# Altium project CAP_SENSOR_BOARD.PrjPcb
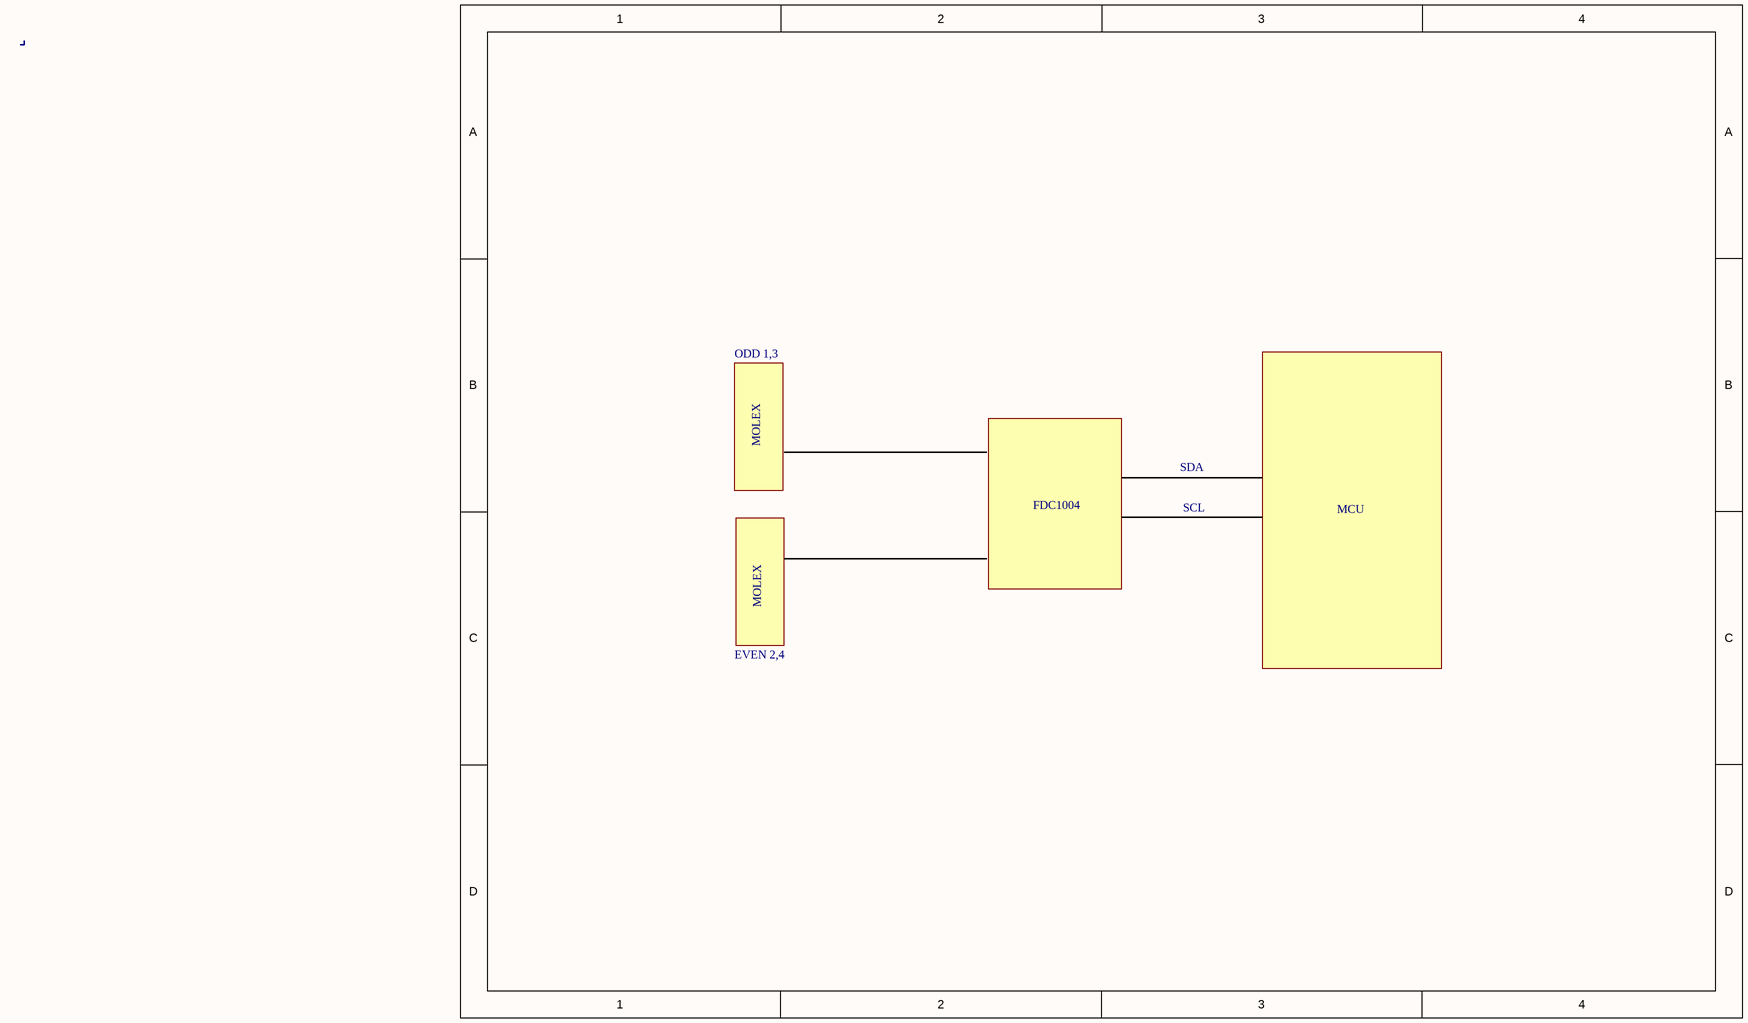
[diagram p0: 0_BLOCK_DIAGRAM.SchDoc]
5 sheets, 54 parts. Net scope: global (net labels, ports and power ports of the same name join across sheets).
Board file: CAP_SENSOR_BOARD.PcbDoc
Sheets:
  0_BLOCK_DIAGRAM.SchDoc
  1_POWER.SchDoc
  2_MCU.SchDoc
  3_PERIPHERAL.SchDoc
  5_UART.SchDoc

## Sheet 0_BLOCK_DIAGRAM.SchDoc
size A; SheetNumber: 1; SheetTotal: 5; ENG_APP_DATE: --/--/--; DSN_APP_DATE: --/--/--; CHK_APP_DATE: --/--/--

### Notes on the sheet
- ODD 1,3
- MOLEX
- SDA
- FDC1004
- SCL
- MCU
- EVEN 2,4

## Sheet 1_POWER.SchDoc: CAP SENSOR BOARD, PCBA
size A; DrawnBy: B. NGAI; Revision: X1; SheetNumber: 2; SheetTotal: 5; ENG_APP_DATE: --/--/--; DSN_APP_DATE: --/--/--; CHK_APP_DATE: --/--/--
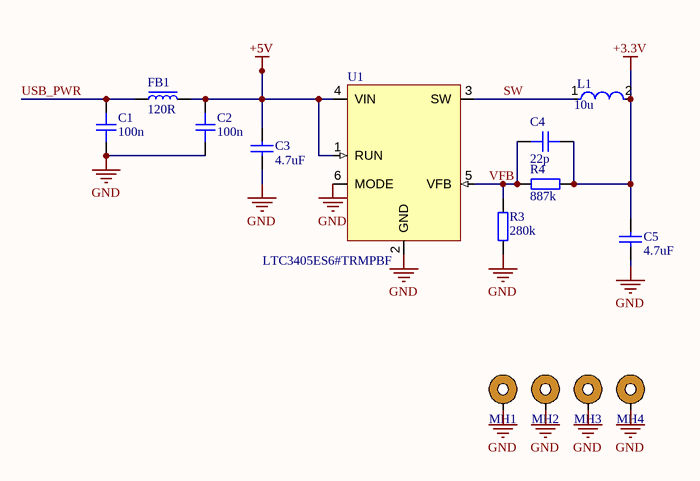
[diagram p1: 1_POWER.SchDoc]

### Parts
C1  100n  [CAP_0603]
C2  100n  [CAP_0603]
C3  4.7uF  [CAPC2013X140X50NL20T25]
C4  22p  [CAP_0603]
C5  4.7uF  [CAPC2013X140X50NL20T25]
FB1  120R  [FB_0603]
L1  10u  [FP-NRH2412-MFG]
MH1  M3-PTH  [MTG_M3_PTH_90317A112]  (value not drawn)  (no BOM)
MH2  M3-PTH  [MTG_M3_PTH_90317A112]  (value not drawn)  (no BOM)
MH3  M3-PTH  [MTG_M3_PTH_90317A112]  (value not drawn)  (no BOM)
MH4  M3-PTH  [MTG_M3_PTH_90317A112]  (value not drawn)  (no BOM)
R3  280k  [RES_0603]
R4  887k  [RES_0603]
U1  LTC3405ES6#TRMPBF  [SOT-23-6]

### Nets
+3.3V: C4.2 C5.2 L1.2 R4.2
+5V: C2.2 C3.2 FB1.2 U1.1(RUN) U1.4(VIN)
GND: C1.1 C2.1 C3.1 C5.1 MH1.1 MH2.1 MH3.1 MH4.1 R3.2 U1.2(GND) U1.6(MODE)
SW: L1.1 U1.3(SW)
USB_PWR: C1.2 FB1.1
VFB: C4.1 R3.1 R4.1 U1.5(VFB)

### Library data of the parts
C1 C2 C4 = CAP_0603: Capacitor SMD 0603
C3 C5 = CMP-2007-03298-1: Manufacturer: Kemet; Part Number: C0805C475K8RACTU
FB1 = FB_0603: Ferrite Bead SMD 0603
L1 = CMP-14484-000582-1: Shielded Wirewound Inductor 10uH 20% 0.51A 0.72Ω SMD; DC Resistance (DCR): 600mR; Current Rating: 450mA; Saturation Current: 810mA; Core Material: Ferrite; Test Frequency: 100kHz; Self Resonant Frequency: 29MHz
MH1-MH4 = MTG_M3_PTH_90317A112: Mounting Screw, M3 x 6mm, Internal Tooth Lock Washer, 90317A112; MFR 1: McMaster-Carr; Component: Mechanical; AJ PN: 30-1029
R3 R4 = RES_0603: Resistor SMD 0603
U1 = LTC3405ES6#TRMPBF: 1.5MHz, 300mA / Synchronous Step-Down / Regulator in ThinSOT; Manufacturer: Analog Devices

## Sheet 2_MCU.SchDoc: CAP SENSOR BOARD, PCBA
size A; DrawnBy: B. NGAI; Revision: X1; SheetNumber: 3; SheetTotal: 5; ENG_APP_DATE: --/--/--; DSN_APP_DATE: --/--/--; CHK_APP_DATE: --/--/--
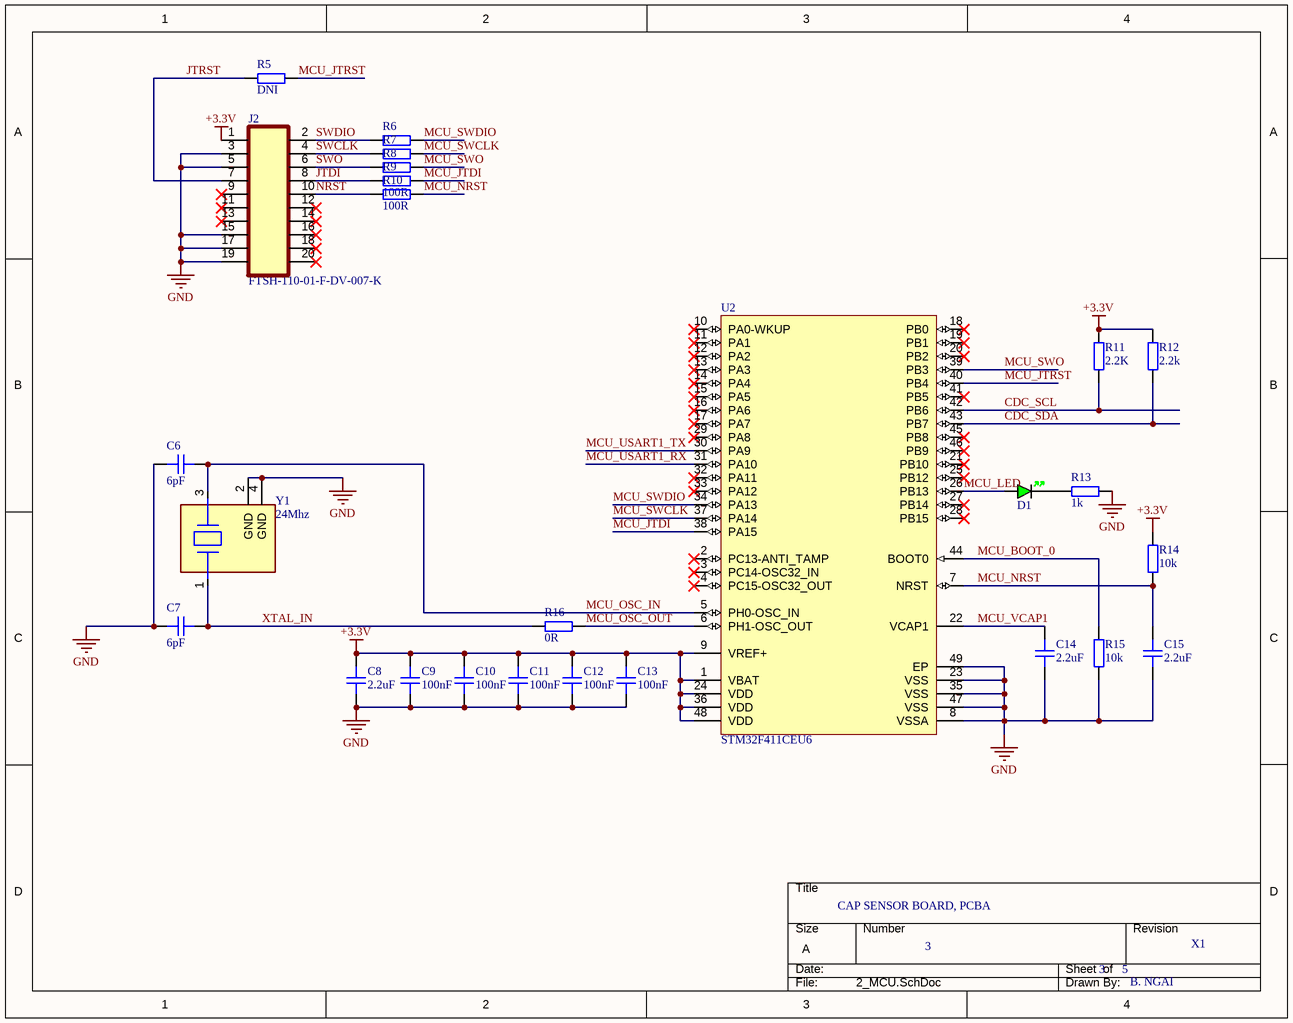
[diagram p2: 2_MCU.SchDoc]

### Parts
C6  6pF  [CAP_0402]
C7  6pF  [CAP_0402]
C8  2.2uF  [CAP_0603]
C9  100nF  [CAP_0402]
C10  100nF  [CAP_0402]
C11  100nF  [CAP_0402]
C12  100nF  [CAP_0402]
C13  100nF  [CAP_0402]
C14  2.2uF  [CAP_0603]
C15  2.2uF  [CAP_0402]
D1  GREEN  [LED_0402_GREEN]  (value not drawn)
J2  MFR 1 PN: FTSH-110-01-F-DV-007-K  [CN_20P_FTSH-110-01-F-DV-007-K]  (hidden comment: CN_20P_FTSH-110-01-F-DV-007-K)
R5  DNI  [RES_0603]
R6  100R  [RES_0402]  (value not drawn)
R7  100R  [RES_0402]  (value not drawn)
R8  100R  [RES_0402]  (value not drawn)
R9  100R  [RES_0402]
R10  100R  [RES_0402]
R11  2.2K  [RES_0402]
R12  2.2k  [RES_0402]
R13  1k  [RES_0603]
R14  10k  [RES_0402]
R15  10k  [RES_0402]
R16  0R  [RES_0402]
U2  STM32F411CEU6  [STM-UFQFPN48_L]
Y1  24Mhz  [FP-ECX-1637-MFG]

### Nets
+3.3V: C8.2 C9.2 C10.2 C11.2 C12.2 C13.2 J2.1 R11.2 R12.2 R14.2 U2.1(VBAT) U2.9(VREF+) U2.24(VDD) U2.36(VDD) U2.48(VDD)
GND: C6.2 C7.2 C8.1 C9.1 C10.1 C11.1 C12.1 C13.1 C14.1 C15.1 J2.3 J2.5 J2.15 J2.17 J2.19 R13.2 R15.1 U2.8(VSSA) U2.23(VSS) U2.35(VSS) U2.47(VSS) U2.49(EP) Y1.2(GND) Y1.4(GND)
CDC_SCL: R11.1 U2.42(PB6)
CDC_SDA: R12.1 U2.43(PB7)
JTDI: J2.8 R9.1
JTRST: J2.7 R5.1
MCU_BOOT_0: R15.2 U2.44(BOOT0)
MCU_JTDI: R9.2 U2.38(PA15)
MCU_JTRST: R5.2 U2.40(PB4)
MCU_LED: D1.A U2.26(PB13)
MCU_NRST: C15.2 R10.2 R14.1 U2.7(NRST)
MCU_OSC_IN: C6.1 U2.5(PH0-OSC_IN) Y1.3(Out/In)
MCU_OSC_OUT: R16.2 U2.6(PH1-OSC_OUT)
MCU_SWCLK: R7.2 U2.37(PA14)
MCU_SWDIO: R6.2 U2.34(PA13)
MCU_SWO: R8.2 U2.39(PB3)
MCU_USART1_RX: U2.31(PA10)
MCU_USART1_TX: U2.30(PA9)
MCU_VCAP1: C14.2 U2.22(VCAP1)
NRST: J2.10 R10.1
SWCLK: J2.4 R7.1
SWDIO: J2.2 R6.1
SWO: J2.6 R8.1
XTAL_IN: C7.1 R16.1 Y1.1(In/Out)
NetD1_K: D1.K R13.1

Not connected (* = marked no-connect by the designer): J2 9* 11* 12* 13* 14* 16* 18* 20*; U2 2(PC13-ANTI_TAMP)* 3(PC14-OSC32_IN)* 4(PC15-OSC32_OUT)* 10(PA0-WKUP)* 11(PA1)* 12(PA2)* 13(PA3)* 14(PA4)* 15(PA5)* 16(PA6)* 17(PA7)* 18(PB0)* 19(PB1)* 20(PB2)* 21(PB10)* 25(PB12)* 27(PB14)* 28(PB15)* 29(PA8)* 32(PA11)* 33(PA12)* 41(PB5)* 45(PB8)* 46(PB9)*

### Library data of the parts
C6 C7 C9-C13 C15 = CAP_0402: Capacitor SMD 0402
C8 C14 = CAP_0603: Capacitor SMD 0603
D1 = LED_0402_GREEN: LED 0402 GREEN SMD
J2 = CN_20P_FTSH-110-01-F-DV-007-K: Connector, Header, 20 Pos, 0.05" Pitch, Vertical, Keyed, SM; MFR 1: Samtec Inc.
R5 = RES_0603: DO NOT INSTALL
R6-R12 R14-R16 = RES_0402: Resistor SMD 0402
R13 = RES_0603: Resistor SMD 0603
U2 = CMP-0243-00165-1: ARM Cortex-M4 32-bit MCU+FPU, 512 KB Flash, 128 KB RAM, 36 I/Os, 48-Pin UFQFPN, -40 to 85 degC, Tray; Operating Frequency(F) (Processor speed) (MHz): 100; FLASH Size (Prog) (kB): 512; Internal RAM Size (kB): 128; I/Os (High Current): 36; Supply Voltage(Vcc) min (V): 1.7
Y1 = CMP-40224-000003-1: CRYSTAL 24.0000MHZ 8PF SMD; Manufacturer: ECS Inc.; Manufacturer Part Number: ECS-240-8-37CKM; Stability: 10ppm; Esr: 80Ω

## Sheet 3_PERIPHERAL.SchDoc: CAP SENSOR BOARD, PCBA
size A; DrawnBy: B. NGAI; Revision: X1; SheetNumber: 4; SheetTotal: 5; ENG_APP_DATE: --/--/--; DSN_APP_DATE: --/--/--; CHK_APP_DATE: --/--/--
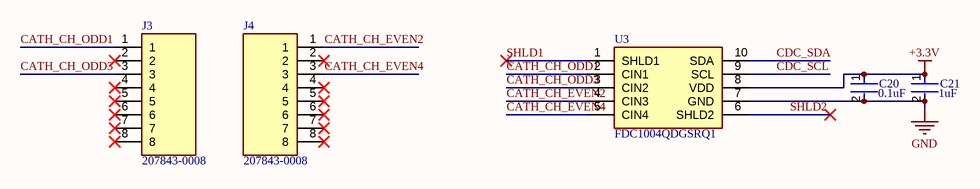
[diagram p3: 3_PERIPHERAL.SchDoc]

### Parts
C20  0.1uF  [FP-CC0603-DA-MFG]
C21  1uF  [FP-CC0603-DA-MFG]
J3  207843-0008  [CN_8P_2078430008]
J4  207843-0008  [CN_8P_2078430008]
U3  FDC1004QDGSRQ1  [SOP50P490X110-10N]

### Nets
+3.3V: C20.1 C21.1 U3.8(VDD)
GND: C20.2 C21.2 U3.7(GND)
CATH_CH_EVEN2: J4.1 U3.4(CIN3)
CATH_CH_EVEN4: J4.3 U3.5(CIN4)
CATH_CH_ODD1: J3.1 U3.2(CIN1)
CATH_CH_ODD3: J3.3 U3.3(CIN2)
CDC_SCL: U3.9(SCL)
CDC_SDA: U3.10(SDA)
SHLD1: U3.1(SHLD1)
SHLD2: U3.6(SHLD2)

Not connected (* = marked no-connect by the designer): J3 2* 4* 5* 6* 7* 8*; J4 2* 4* 5* 6* 7* 8*

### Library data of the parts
C20 = CMP-03422-001304-1: CAP CER 0.1UF 16V X7R 0603; Manufacturer: YAGEO; Manufacturer Part Number: CC0603KPX7R7BB104; Tolerance: 0.1; Material: Ceramic; Value: 100 nF; Temperature Coefficient: 15%
C21 = CMP-03422-000924-1: CAP CER 1UF 16V X7R 0603; Manufacturer: YAGEO; Manufacturer Part Number: CC0603KRX7R7BB105; Tolerance: 0.1; Temperature Coefficient: 15%; Material: Ceramic
J3 J4 = 207843-0008: Connector; Manufacturer_Name: Molex
U3 = FDC1004QDGSRQ1: Integrated Circuit; Manufacturer_Name: Texas Instruments

## Sheet 5_UART.SchDoc: CAP SENSOR BOARD, PCBA
size A; DrawnBy: B. NGAI; Revision: X1; SheetNumber: 5; SheetTotal: 5; ENG_APP_DATE: --/--/--; DSN_APP_DATE: --/--/--; CHK_APP_DATE: --/--/--
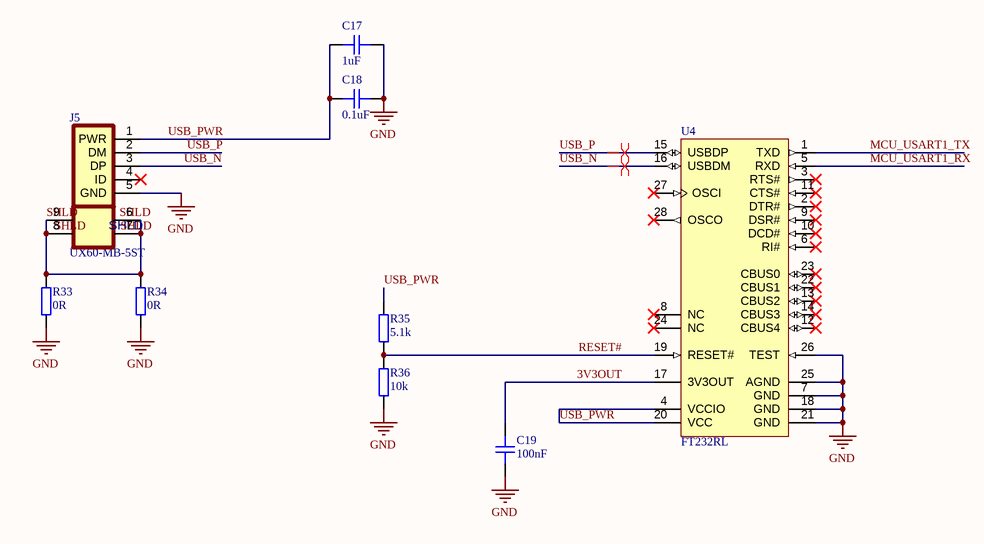
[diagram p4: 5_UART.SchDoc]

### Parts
C17  1uF  [CAP_0402]
C18  0.1uF  [CAP_0402]
C19  100nF  [CAP_0402]
J5  MFR 1 PN: UX60-MB-5ST  [CN_5P_UX60-MB-5ST]  (hidden comment: CN_5P_USB_UX60-MB-5ST)
R33  0R  [RES_0402]
R34  0R  [RES_0402]
R35  5.1k  [RES_0402]
R36  10k  [RES_0402]
U4  FT232RL  [FTDI-SSOP-28_M]

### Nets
GND: C17.2 C18.2 C19.1 J5.5(GND) R33.1 R34.1 R36.1 U4.7(GND) U4.18(GND) U4.21(GND) U4.25(AGND) U4.26(TEST)
3V3OUT: C19.2 U4.17(3V3OUT)
MCU_USART1_RX: U4.5(RXD)
MCU_USART1_TX: U4.1(TXD)
RESET#: R35.1 R36.2 U4.19(RESET#)
SHLD: J5.6 J5.7 J5.8 J5.9 R33.2 R34.2
USB_N: J5.3(DP) U4.16(USBDM)
USB_P: J5.2(DM) U4.15(USBDP)
USB_PWR: C17.1 C18.1 J5.1(PWR) R35.2 U4.4(VCCIO) U4.20(VCC)

Not connected (* = marked no-connect by the designer): J5 4(ID)*; U4 2(DTR#)* 3(RTS#)* 6(RI#)* 8(NC)* 9(DSR#)* 10(DCD#)* 11(CTS#)* 12(CBUS4)* 13(CBUS2)* 14(CBUS3)* 22(CBUS1)* 23(CBUS0)* 24(NC)* 27(OSCI)* 28(OSCO)*

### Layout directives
differential pair: USB_N, USB_P

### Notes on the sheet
- Labels drawn without touching a wire or pin: SHLD

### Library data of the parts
C17-C19 = CAP_0402: Capacitor SMD 0402
J5 = CN_5P_UX60-MB-5ST: MFR 1: Hirose Electric Co Ltd
R33-R36 = RES_0402: Resistor SMD 0402
U4 = CMP-2000-05029-1: IC USB FS SERIAL UART 28-SSOP; Manufacturer: FTDI; Receive FIFO: 256B; Number of Channels per Chip: 1; Maximum Data Rate: 3MBd; Transmit FIFO: 128B

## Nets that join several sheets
+3.3V: 1_POWER (C4.2 C5.2 L1.2 R4.2), 2_MCU (15 pins), 3_PERIPHERAL (C20.1 C21.1 U3.8)
GND: 1_POWER (11 pins), 2_MCU (24 pins), 3_PERIPHERAL (C20.2 C21.2 U3.7), 5_UART (12 pins)
CDC_SCL: 2_MCU (R11.1 U2.42), 3_PERIPHERAL (U3.9)
CDC_SDA: 2_MCU (R12.1 U2.43), 3_PERIPHERAL (U3.10)
MCU_USART1_RX: 2_MCU (U2.31), 5_UART (U4.5)
MCU_USART1_TX: 2_MCU (U2.30), 5_UART (U4.1)
USB_PWR: 1_POWER (C1.2 FB1.1), 5_UART (6 pins)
